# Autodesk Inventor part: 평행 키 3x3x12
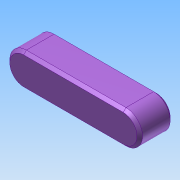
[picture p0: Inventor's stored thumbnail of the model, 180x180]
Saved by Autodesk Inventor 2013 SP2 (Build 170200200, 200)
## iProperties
Created: 2025-10
Part Number: 평행 키 3x3x12
Material: Generic
Document SubType Name: Modeling
Designer: a
Density: 1 g/cm^3
Author: a
변환 표준: STEP AP214IS
전처리기: Build: 200, Release: 2013 SP2 Update 6 - Date: Thu 07/17/2014
전송 단위: 밀리미터
불확실성: 0.01
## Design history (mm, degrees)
node "평행 키 3x3x121"
body "Solid1"
node "기준1"
